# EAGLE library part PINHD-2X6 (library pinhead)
PIN HEADER
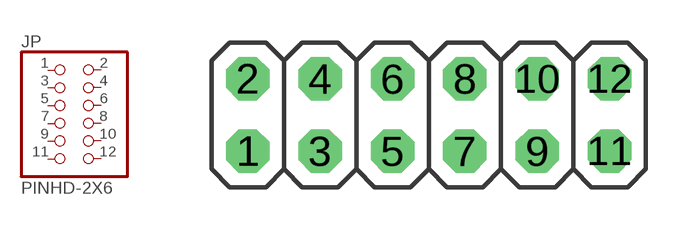
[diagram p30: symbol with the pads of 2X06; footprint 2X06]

Designator prefix JP

## PINHD-2X6  [2X06]
1  1  pas
2  2  pas
3  3  pas
4  4  pas
5  5  pas
6  6  pas
7  7  pas
8  8  pas
9  9  pas
10  10  pas
11  11  pas
12  12  pas

## Footprint 2X06 (pad centres in mm)
PIN HEADER
drill 1.016 octagon: 1 -6.35,-1.27; 2 -6.35,1.27; 3 -3.81,-1.27; 4 -3.81,1.27; 5 -1.27,-1.27; 6 -1.27,1.27; 7 1.27,-1.27; 8 1.27,1.27; 9 3.81,-1.27; 10 3.81,1.27; 11 6.35,-1.27; 12 6.35,1.27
